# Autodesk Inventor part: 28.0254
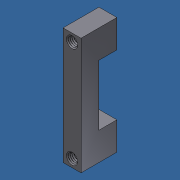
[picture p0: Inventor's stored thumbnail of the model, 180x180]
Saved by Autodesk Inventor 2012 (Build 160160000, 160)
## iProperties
Created: 2011-10
Part Number: 28.0254
Document SubType Name: Modeling
Designer: Administrator
Density: 7.85 g/cm^3
Material: Steel
Description: NUT SLIDE CONNECTOR 16
Mass: 35.0806 g
Surface Area: 30.1188 cm^2
Volume: 4.46886 cm^3
Vendor: S
Translation Standard: STEP AP214IS
FileName: 28-0254-0.stp
PreProcessor: Mechanical Desktop 2011
PostProcessor: Build: 236a, Release: 2009 RTM - Date: Fri 02/22/2008
Sent Units: MM
Uncertainty: 1.0000000000000002e-06
Author: Administrator
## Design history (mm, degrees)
feature "Base1"
body "Solid1"
